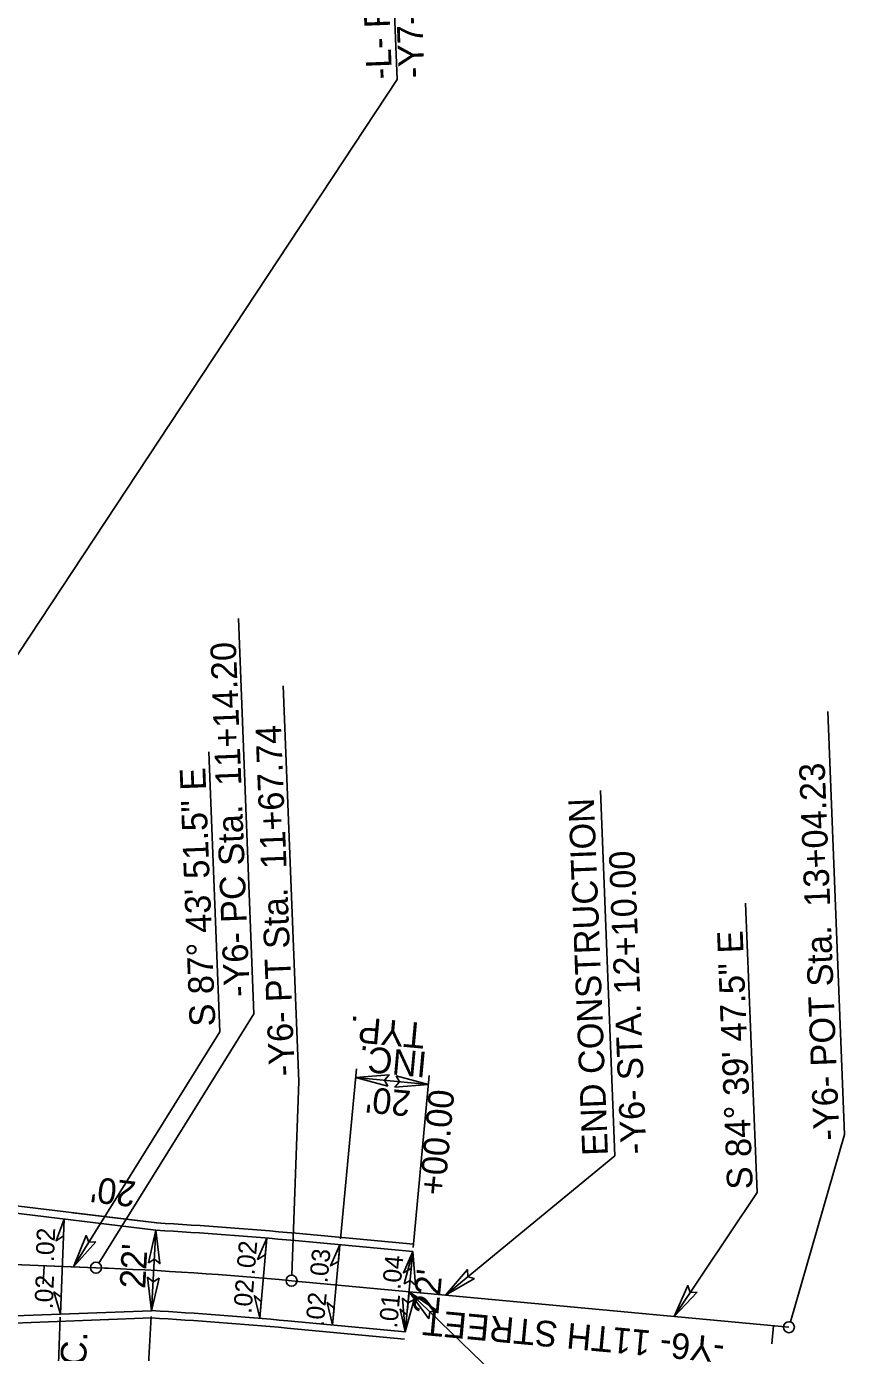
# Model space of a CAD drawing. Extents: x 1627861 to 1629601, y 761281 to 766239.
# Drawn here: x 1628539 to 1628762.4, y 763149.5 to 763511.7 of the extents above; entities that cross this region are included whole.
import ezdxf

# ---------------------------------------------------------------- set-up
doc = ezdxf.new("R2010")
doc.units = 0
for name, color, linetype in [('Cogo Default Point CELL', 7, 'Continuous'), ('Exist Other Culture Sign Leader', 7, 'Continuous'), ('Exist Property Tie Line Text', 7, 'Continuous'), ('Exist Right of Way Line Leader', 7, 'Continuous'), ('Exist Right of Way Monument Text', 7, 'Continuous'), ('Exist Utilities Gas Meter CELL', 7, 'Continuous'), ('Exist Utilities Gas Meter Cogo Number', 7, 'Continuous'), ('Exist Utilities Power UG Cable SUE LOS B Cogo Point CELL', 7, 'Continuous'), ('Exist Utilities Telephone UG Cable SUE LOS B Cogo Point CELL', 7, 'Continuous'), ('Exist Utilities Water UG Line SUE LOS B Cogo Number', 7, 'Continuous'), ('Scratch_Level_0', 7, 'Continuous'), ('Typical Terminator CELL', 7, 'Continuous')]:
    doc.layers.add(name, color=color, linetype=linetype)

msp = doc.modelspace()

# ---------------------------------------------------------------- linework, layer by layer
at = {"layer": 'Exist Other Culture Sign Leader'}
for p in [(1628695.79, 763303.03), (1628653.43, 763165.16)]:
    msp.add_line(p, (1628699.73, 763203.17), dxfattribs=at)
at = {"layer": 'Exist Property Tie Line Text'}
for p, q in [((1628543.75, 763173.2), (1628543.55, 763168.21)), ((1628643.48, 763166.09), (1628643.01, 763161.11)), ((1628743.04, 763156.79), (1628742.58, 763151.81))]:
    msp.add_line(p, q, dxfattribs=at)
at = {"layer": 'Exist Right of Way Line Leader'}
for p, q in [((1628640.24, 763497.24), (1628635.31, 763622.14)), ((1628444.09, 763200.16), (1628640.24, 763497.24)), ((1628601.1, 763241.97), (1628596.85, 763349.97)), ((1628613.35, 763223.54), (1628609.09, 763331.59)), ((1628762.43, 763209.06), (1628757.87, 763324.57)), ((1628591.77, 763237.09), (1628588.75, 763313.52)), ((1628738.55, 763193.19), (1628735.43, 763272.24)), ((1628558.74, 763173.92), (1628601.1, 763241.97)), ((1628551.84, 763172.88), (1628591.77, 763237.09)), ((1628611.41, 763170.59), (1628613.35, 763223.54)), ((1628747.67, 763157.84), (1628762.43, 763209.06)), ((1628738.55, 763193.19), (1628715.92, 763159.32))]:
    msp.add_line(p, q, dxfattribs=at)
for centre in [(1628557.94, 763172.64), (1628611.36, 763169.09), (1628747.25, 763156.4)]:
    msp.add_circle(centre, 1.5, dxfattribs=at)
at = {"layer": 'Exist Right of Way Monument Text'}
for p, q in [((1628524.36, 763188.98), (1628574.33, 763182.88)), ((1628612.38, 763180.04), (1628644.5, 763177.04)), ((1628523.17, 763159.01), (1628573.11, 763160.91)), ((1628610.34, 763158.14), (1628642.45, 763155.14))]:
    msp.add_line(p, q, dxfattribs=at)
for radius in [1011, 989]:
    msp.add_arc((1628518.35, 762173.43), radius, 84.66319, 86.82578, dxfattribs=at)
at = {"layer": 'Exist Utilities Gas Meter CELL'}
for p, q in [((1628443.83, 763177.16), (1628562.52, 763172.46)), ((1628443.83, 763177.16), (1628557.94, 763172.64)), ((1628443.83, 763177.16), (1628557.94, 763172.64)), ((1628611.36, 763169.09), (1628747.25, 763156.4)), ((1628611.36, 763169.09), (1628747.25, 763156.4))]:
    msp.add_line(p, q, dxfattribs=at)
msp.add_arc((1628518.35, 762173.43), 1000, 84.66319, 87.73097, dxfattribs=at)
msp.add_arc((1628518.35, 762173.43), 1000, 84.66319, 87.73097, dxfattribs=at)
at = {"layer": 'Exist Utilities Gas Meter Cogo Number'}
for points in [[(1628637.67, 763222.19), (1628628.85, 763224.57), (1628638.01, 763225.33), (1628636.72, 763223.84)], [(1628639.95, 763225.1), (1628648.77, 763222.71), (1628639.61, 763221.96), (1628640.9, 763223.45)], [(1628557.91, 763179.71), (1628551.84, 763172.88), (1628555.26, 763181.41), (1628556.02, 763179.59)], [(1628572.29, 763173.98), (1628574.33, 763182.88), (1628575.43, 763173.75), (1628573.89, 763174.99)], [(1628642.12, 763168.23), (1628644.5, 763177.04), (1628645.25, 763167.88), (1628643.77, 763169.18)], [(1628661.37, 763169.67), (1628653.43, 763165.16), (1628659.41, 763172.14), (1628659.54, 763170.17)], [(1628575.16, 763169.81), (1628573.11, 763160.91), (1628572.02, 763170.03), (1628573.55, 763168.8)], [(1628722.21, 763165.95), (1628715.92, 763159.32), (1628719.61, 763167.74), (1628720.31, 763165.89)], [(1628644.83, 763163.96), (1628642.45, 763155.14), (1628641.7, 763164.3), (1628643.19, 763163.01)], [(1628648.87, 763158.72), (1628643.48, 763166.09), (1628651.1, 763160.96), (1628649.16, 763160.6)]]:
    msp.add_lwpolyline(points, close=True, dxfattribs=at)
at = {"layer": 'Exist Utilities Telephone UG Cable SUE LOS B Cogo Point CELL'}
for p, q in [((1628524.6, 763190.97), (1628574.57, 763184.86)), ((1628612.57, 763182.04), (1628644.69, 763179.04)), ((1628523.25, 763157.01), (1628573.19, 763158.91)), ((1628610.15, 763156.15), (1628642.27, 763153.15))]:
    msp.add_line(p, q, dxfattribs=at)
for radius in [1013, 987]:
    msp.add_arc((1628518.35, 762173.43), radius, 84.66319, 86.82578, dxfattribs=at)
at = {"layer": 'Exist Utilities Water UG Line SUE LOS B Cogo Number'}
for p, q in [((1628549.26, 763185.94), (1628548.23, 763159.96)), ((1628602.71, 763158.82), (1628604.59, 763180.74)), ((1628622.54, 763157), (1628624.59, 763178.9)), ((1628642.45, 763155.14), (1628644.5, 763177.04))]:
    msp.add_line(p, q, dxfattribs=at)
at = {"layer": 'Scratch_Level_0'}
for p, q in [((1628624.74, 763180.51), (1628629.08, 763227)), ((1628628.85, 763224.57), (1628648.77, 763222.71)), ((1628644.6, 763178.12), (1628648.99, 763225.11)), ((1628551.61, 763187.67), (1628571.46, 763185.24)), ((1628574.33, 763182.88), (1628573.11, 763160.91)), ((1628642.45, 763155.14), (1628644.5, 763177.04)), ((1628643.48, 763166.09), (1628685.91, 763125.1)), ((1628548.2, 763159.16), (1628546.74, 763122.35)), ((1628569.76, 763100.47), (1628573.02, 763159.29))]:
    msp.add_line(p, q, dxfattribs=at)
at = {"layer": 'Typical Terminator CELL'}
for points in [[(1628549.26, 763185.94), (1628547.02, 763180.02), (1628549.08, 763181.32)], [(1628604.59, 763180.74), (1628602.08, 763174.93), (1628604.19, 763176.13)], [(1628624.59, 763178.9), (1628622.04, 763173.12), (1628624.16, 763174.3)], [(1628644.5, 763177.04), (1628641.95, 763171.26), (1628644.07, 763172.44)], [(1628548.23, 763159.96), (1628546.47, 763166.04), (1628548.41, 763164.58)], [(1628602.71, 763158.82), (1628601.23, 763164.97), (1628603.1, 763163.43)], [(1628622.54, 763157), (1628621.11, 763163.16), (1628622.97, 763161.6)], [(1628642.45, 763155.14), (1628641.02, 763161.3), (1628642.88, 763159.74)]]:
    msp.add_lwpolyline(points, close=True, dxfattribs=at)

# ---------------------------------------------------------------- texts
at = {"layer": 'Cogo Default Point CELL'}
for s, p in [('S 87%%d 43\' 51.5" E', (1628590.58, 763238.64)), ('S 84%%d 39\' 47.5" E', (1628737.39, 763194.15))]:
    msp.add_text(s, height=7, rotation=92.2582, dxfattribs=at).set_placement(p)
at = {"layer": 'Exist Other Culture Sign Leader'}
for s, rotation, p in [('END CONSTRUCTION', 92.2582, (1628697.82, 763203.36)), ('-Y6- STA. 12+10.00', 92.2582, (1628708.31, 763203.77)), ('-Y6- 11TH STREET', 174.6632, (1628729.92, 763153.57))]:
    msp.add_text(s, height=7, rotation=rotation, dxfattribs=at).set_placement(p)
at = {"layer": 'Exist Right of Way Line Leader'}
for s, p in [('-Y7- POT Sta.  11+74.40', (1628647.71, 763497.7)), ('-L- POT Sta. 27+24.58=', (1628638.84, 763497.35)), ('-Y6- PC Sta.  11+14.20', (1628599.96, 763246.72)), ('-Y6- PT Sta.  11+67.74', (1628612.26, 763225.07)), ('-Y6- POT Sta.  13+04.23', (1628761.06, 763207.49))]:
    msp.add_text(s, height=7, rotation=92.2582, dxfattribs=at).set_placement(p)
at = {"layer": 'Exist Utilities Power UG Cable SUE LOS B Cogo Point CELL'}
for s, rotation, p in [('TYP.', 174.6632, (1628648.07, 763239.43)), ('INC.', 174.6632, (1628648.61, 763231.54)), ("20'", 174.6632, (1628644.19, 763220.91)), ('+00.00', 84.6632, (1628653.21, 763192.2)), ("22'", 86.8258, (1628571.38, 763166.79)), ("22'", 84.6632, (1628651.46, 763159.72)), ("20' INC.", 86.8258, (1628553.81, 763121.6))]:
    msp.add_text(s, height=7, rotation=rotation, dxfattribs=at).set_placement(p)
at = {"layer": 'Exist Utilities Water UG Line SUE LOS B Cogo Number'}
for s, rotation, p in [('.02', 87.731, (1628546.45, 763174.16)), ('.02', 85.1069, (1628601.23, 763170.52)), ('.03', 84.6632, (1628621.17, 763168.34)), ('.04', 84.6632, (1628641.09, 763166.54)), ('.02', 87.731, (1628546.12, 763161.25)), ('.02', 85.1069, (1628600.38, 763160.01)), ('.02', 84.6632, (1628620.14, 763156.44)), ('.01', 84.6632, (1628640.19, 763156.01))]:
    msp.add_text(s, height=5, rotation=rotation, dxfattribs=at).set_placement(p)
at = {"layer": 'Scratch_Level_0'}
msp.add_text("20'", height=7, rotation=173.0248, dxfattribs=at).set_placement((1628569.15, 763196.09))

doc.saveas('drawing.dxf')
